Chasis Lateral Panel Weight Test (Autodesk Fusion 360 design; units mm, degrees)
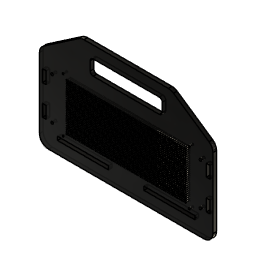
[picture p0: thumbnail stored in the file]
sketch "Sketch1" plane through (0, 0, 0) normal (0, 1, 0) x axis (1, 0, 0)
  line L1 (88.4625, -157.8495) -> (88.4625, -182.8495)
  line L2 (73.4625, -202.8495) -> (-2.8014, -202.7605)
  line L3 (3.9625, -155.3495) -> (292.9625, -155.3495)
  line L4 (3.9625, -91.4325) -> (148.4625, -91.4325)
  line L5 (148.4625, -147.4325) -> (148.4625, -35.4325)
  line L6 (292.9625, -15.4325) -> (3.9625, -15.4325)
  line L7 (262.9625, -141.4325) -> (33.9625, -141.4325)
  line L8 (88.4625, -182.8495) -> (208.4625, -182.8495)
  line L9 (3.9625, -35.4325) -> (292.9625, -35.4325)
  line L10 (292.9625, -91.4325) -> (148.4625, -91.4325)
  line L11 (3.9625, -155.3495) -> (3.9625, -252.9325)
  line L12 (148.4625, -214.9325) -> (148.4625, -182.8495)
  line L13 (223.4625, -202.8495) -> (299.7264, -202.7605)
  line L14 (148.4625, -170.3495) -> (148.4625, -155.3495)
  line L15 (208.4625, -157.8495) -> (88.4625, -157.8495)
  line L16 (3.9625, -147.4325) -> (3.9625, -35.4325)
  line L17 (262.9625, -41.4325) -> (262.9625, -35.4325)
  line L18 (88.4625, -182.8495) -> (208.4625, -157.8495)
  line L19 (3.9625, -147.4325) -> (3.9625, -155.3495)
  line L20 (88.4625, -157.8495) -> (208.4625, -182.8495)
  line L21 (33.9625, -141.4325) -> (33.9625, -147.4325)
  line L22 (33.9625, -41.4325) -> (33.9625, -35.4325)
  line L23 (208.4625, -182.8495) -> (208.4625, -157.8495)
  line L24 (292.9625, -35.4325) -> (292.9625, -15.4325)
  line L25 (292.9625, -155.3495) -> (292.9625, -252.9325)
  line L26 (292.9625, -155.3495) -> (292.9625, -147.4325)
  line L27 (292.9625, -35.4325) -> (292.9625, -147.4325)
  line L28 (262.9625, -141.4325) -> (262.9625, -147.4325)
  line L29 (3.9625, -15.4325) -> (3.9625, -35.4325)
  line L30 (292.9625, -147.4325) -> (3.9625, -147.4325)
  line L31 (262.9625, -147.4325) -> (33.9625, -147.4325)
  line L32 (223.4625, -202.8495) -> (73.4625, -202.8495)
  line L33 (422.8306, -56.4325) -> (416.8306, -56.4325)
  line L34 (470.8306, -141.4325) -> (422.8306, -141.4325)
  line L35 (422.8306, -56.4325) -> (422.8306, -41.4325)
  line L36 (470.8306, -41.4325) -> (422.8306, -41.4325)
  line L37 (550.8306, -41.4325) -> (550.8306, -35.4325)
  line L38 (416.8306, -126.4325) -> (422.8306, -126.4325)
  line L39 (470.8306, -147.4325) -> (470.8306, -141.4325)
  line L40 (684.8306, -147.4325) -> (604.8306, -147.4325)
  line L41 (416.8306, -56.4325) -> (416.8306, -126.4325)
  line L42 (684.8306, -41.4325) -> (732.8306, -41.4325)
  line L43 (422.8306, -126.4325) -> (422.8306, -141.4325)
  line L44 (684.8306, -41.4325) -> (684.8306, -35.4325)
  line L45 (738.8306, -126.4325) -> (732.8306, -126.4325)
  line L46 (604.8306, -147.4325) -> (604.8306, -141.4325)
  line L47 (684.8306, -35.4325) -> (604.8306, -35.4325)
  line L48 (470.8306, -35.4325) -> (470.8306, -41.4325)
  line L49 (732.8306, -126.4325) -> (732.8306, -141.4325)
  line L50 (604.8306, -35.4325) -> (604.8306, -41.4325)
  line L51 (550.8306, -41.4325) -> (604.8306, -41.4325)
  line L52 (550.8306, -141.4325) -> (550.8306, -147.4325)
  line L53 (732.8306, -56.4325) -> (732.8306, -41.4325)
  line L54 (550.8306, -35.4325) -> (470.8306, -35.4325)
  line L55 (732.8306, -56.4325) -> (738.8306, -56.4325)
  line L56 (550.8306, -147.4325) -> (470.8306, -147.4325)
  line L57 (684.8306, -141.4325) -> (684.8306, -147.4325)
  line L58 (738.8306, -56.4325) -> (738.8306, -126.4325)
  line L59 (684.8306, -141.4325) -> (732.8306, -141.4325)
  line L60 (550.8306, -141.4325) -> (604.8306, -141.4325)
  line L61 (3.9625, -155.3495) -> (3.9625, -147.4325)
  line L62 (3.9625, -155.3495) -> (73.4625, -202.8495)
  line L63 (292.9625, -155.3495) -> (223.4625, -202.8495)
  line L64 (292.9625, -155.3495) -> (292.9625, -147.4325)
  line L65 (281.9625, -126.4325) -> (287.9625, -126.4325)
  line L66 (287.9625, -56.4325) -> (281.9625, -56.4325)
  line L67 (8.9625, -126.4325) -> (14.9625, -126.4325)
  line L68 (14.9625, -56.4325) -> (8.9625, -56.4325)
  line L69 (14.9625, -91.4325) -> (281.9625, -91.4325)
  line L70 (148.4625, -71.6893) -> (148.4625, -91.4325)
  line L71 (287.9625, -56.4325) -> (281.9625, -56.4325)
  line L72 (14.9625, -91.4325) -> (281.9625, -91.4325)
  line L73 (281.9625, -126.4325) -> (287.9625, -126.4325)
  line L74 (8.9625, -126.4325) -> (14.9625, -126.4325)
  line L75 (148.4625, -71.6893) -> (148.4625, -91.4325)
  line L76 (14.9625, -56.4325) -> (8.9625, -56.4325)
  line L77 (-57.8702, -329.7432) -> (-63.8702, -329.7432)
  line L78 (-336.8702, -329.7432) -> (-336.8702, -399.7432)
  line L79 (-330.8702, -364.7432) -> (-63.8702, -364.7432)
  line L80 (-63.8702, -399.7432) -> (-57.8702, -399.7432)
  line L81 (-63.8702, -329.7432) -> (-63.8702, -399.7432)
  line L82 (-336.8702, -399.7432) -> (-330.8702, -399.7432)
  line L83 (-57.8702, -399.7432) -> (-57.8702, -329.7432)
  line L84 (-330.8702, -399.7432) -> (-330.8702, -329.7432)
  line L85 (-197.3702, -345) -> (-197.3702, -364.7432)
  line L86 (-330.8702, -329.7432) -> (-336.8702, -329.7432)
  line L87 (732.8306, -106.4325) -> (738.8306, -106.4325)
  line L88 (732.8306, -106.4325) -> (732.8306, -76.4325)
  line L89 (732.8306, -76.4325) -> (738.8306, -76.4325)
  line L90 (422.8306, -106.4325) -> (416.8306, -106.4325)
  line L91 (422.8306, -106.4325) -> (422.8306, -76.4325)
  line L92 (422.8306, -76.4325) -> (416.8306, -76.4325)
  line L93 (732.8306, -91.4325) -> (422.8306, -91.4325)
  line L94 (738.8306, -91.4325) -> (732.8306, -91.4325)
  line L95 (760, -91.4325) -> (738.8306, -91.4325)
  line L96 (-80, -106.4325) -> (416.8306, -106.4325)
  line L97 (-80, -76.4325) -> (416.8306, -76.4325)
  line L98 (8.9625, -106.4325) -> (14.9625, -106.4325)
  line L99 (14.9625, -76.4325) -> (14.9625, -56.4325)
  line L100 (14.9625, -126.4325) -> (14.9625, -106.4325)
  line L101 (8.9625, -106.4325) -> (8.9625, -126.4325)
  line L102 (8.9625, -56.4325) -> (8.9625, -76.4325)
  line L103 (14.9625, -76.4325) -> (14.9625, -56.4325)
  line L104 (14.9625, -126.4325) -> (14.9625, -106.4325)
  line L105 (8.9625, -106.4325) -> (8.9625, -126.4325)
  line L106 (8.9625, -56.4325) -> (8.9625, -76.4325)
  line L107 (281.9625, -106.4325) -> (281.9625, -126.4325)
  line L108 (281.9625, -56.4325) -> (281.9625, -76.4325)
  line L109 (287.9625, -76.4325) -> (287.9625, -56.4325)
  line L110 (287.9625, -126.4325) -> (287.9625, -106.4325)
  line L111 (287.9625, -76.4325) -> (287.9625, -56.4325)
  line L112 (287.9625, -126.4325) -> (287.9625, -106.4325)
  line L113 (281.9625, -106.4325) -> (281.9625, -126.4325)
  line L114 (281.9625, -56.4325) -> (281.9625, -76.4325)
  line L115 (287.9625, -106.4325) -> (281.9625, -106.4325)
  line L116 (284.9625, -91.4325) -> (284.9625, -106.4325)
  line L117 (11.9625, -91.4325) -> (11.9625, -106.4325)
  line L118 (287.9625, -76.4325) -> (281.9625, -76.4325)
  line L119 (14.9625, -76.4325) -> (8.9625, -76.4325)
  line L120 (118.9625, -41.4325) -> (33.9625, -41.4325)
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  point P18 (262.9625, -35.4325)
  point P17 (33.9625, -35.4325)
  point P30 (148.4625, -147.4325)
  point P22 (148.4625, -91.4325)
  point P6 (262.9625, -147.4325)
  point P7 (262.9625, -141.4325)
  point P16 (262.9625, -41.4325)
  point P5 (33.9625, -147.4325)
  point P8 (33.9625, -141.4325)
  point P29 (33.9625, -41.4325)
  point P10 (148.4625, -155.3495)
  point P35 (148.4625, -170.3495)
  point P9 (148.4625, -170.3495)
  point P26 (148.4625, -182.8495)
  point P15 (-2.8014, -202.7605)
  point P36 (299.7264, -202.7605)
  point P13 (73.4625, -202.8495)
  point P37 (223.4625, -202.8495)
  point P20 (3.9625, -91.4325)
  point P81 (148.4625, -91.4325)
  point P93 (148.4625, -91.4325)
  point P103 (-63.8702, -364.7432)
  point P104 (-330.8702, -364.7432)
  point P105 (-197.3702, -364.7432)
  point P115 (422.8306, -91.4325)
  point P116 (732.8306, -91.4325)
  point P118 (738.8306, -91.4325)
  point P122 (14.9625, -106.4325)
  point P123 (8.9625, -106.4325)
  point P92 (14.9625, -91.4325)
  point P124 (281.9625, -106.4325)
  point P91 (281.9625, -91.4325)
  point P125 (287.9625, -106.4325)
  point P79 (281.9625, -91.4325)
  point P126 (284.9625, -106.4325)
  point P128 (11.9625, -106.4325)
  point P130 (287.9625, -76.4325)
  point P131 (281.9625, -76.4325)
  point P132 (14.9625, -76.4325)
  point P133 (8.9625, -76.4325)
  point P129 (11.9625, -91.4325)
  point P134 (11.9625, -91.4325)
  point P127 (284.9625, -91.4325)
  point P135 (284.9625, -91.4325)
  point P140 (148.4625, -38.4325)
  point P142 (148.4625, -38.4325)
  point P3 (292.9625, -15.4325)
  point P19 (292.9625, -35.4325)
  point P2 (3.9625, -147.4325)
  point P24 (3.9625, -35.4325)
  point P14 (292.9625, -155.3495)
  point P27 (292.9625, -147.4325)
  point P32 (208.4625, -182.8495)
  point P33 (88.4625, -182.8495)
  point P28 (88.4625, -157.8495)
  point P4 (3.9625, -15.4325)
  point P63 (470.8306, -141.4325)
  point P64 (470.8306, -147.4325)
  point P42 (416.8306, -126.4325)
  point P57 (422.8306, -126.4325)
  point P47 (550.8306, -35.4325)
  point P61 (470.8306, -35.4325)
  point P40 (470.8306, -41.4325)
  point P48 (422.8306, -41.4325)
  point P53 (550.8306, -41.4325)
  point P58 (604.8306, -41.4325)
  point P66 (416.8306, -56.4325)
  point P51 (422.8306, -141.4325)
  point P1 (0, 0)
  point P71 (287.9625, -126.4325)
  point P72 (281.9625, -126.4325)
  point P74 (287.9625, -56.4325)
  point P75 (14.9625, -126.4325)
  point P76 (8.9625, -126.4325)
  point P78 (14.9625, -56.4325)
  point P83 (287.9625, -126.4325)
  point P84 (281.9625, -126.4325)
  point P85 (287.9625, -56.4325)
  point P89 (14.9625, -126.4325)
  point P90 (8.9625, -126.4325)
  point P88 (14.9625, -56.4325)
  point P95 (-57.8702, -399.7432)
  point P96 (-63.8702, -399.7432)
  point P97 (-57.8702, -329.7432)
  point P101 (-330.8702, -399.7432)
  point P102 (-336.8702, -399.7432)
  point P100 (-330.8702, -329.7432)
  point P108 (732.8306, -106.4325)
  point P109 (738.8306, -106.4325)
  point P110 (732.8306, -76.4325)
  point P114 (738.8306, -76.4325)
  point P136 (118.9625, -41.4325)
  point P137 (177.9625, -41.4325)
  point P138 (118.9625, -35.4325)
  perpendicular L6 L24
  perpendicular L9 L24
  perpendicular L6 L29
  coincident P18 L9
  perpendicular L9 L17
  coincident P17 L9
  perpendicular L9 L22
  perpendicular L9 L16
  perpendicular L24 L30
  perpendicular L9 L27
  midpoint P30 L30
  midpoint P22 L5
  symmetric P6 P18 L10
  symmetric P7 P16 L10
  symmetric P5 P17 L10
  symmetric P8 P29 L10
  perpendicular L26 L30
  perpendicular L3 L26
  perpendicular L19 L30
  midpoint P10 L3
  perpendicular L3 L14
  perpendicular L8 L23
  parallel L1 L23
  parallel L8 L15
  coincident P35 L18
  coincident P35 L20
  coincident P9 P35
  midpoint P26 L8
  perpendicular L8 L12
  perpendicular L3 L25
  perpendicular L3 L11
  symmetric P15 P36 L5
  symmetric P13 P37 L5
  midpoint P20 L16
  parallel L8 L32
  parallel L6 L32
  perpendicular L38 L43
  perpendicular L38 L41
  parallel L36 L54
  parallel L36 L51
  parallel L47 L51
  parallel L42 L47
  equal L37 L48
  equal L44 L50
  equal L45 L55
  equal L47 L54
  equal L35 L43
  parallel L54 L56
  parallel L40 L47
  parallel L42 L59
  parallel L51 L60
  parallel L43 L49
  parallel L35 L53
  equal L36 L42
  equal L48 L50
  equal L41 L58
  equal L35 L53
  equal L43 L49
  collinear L34 L60
  collinear L59 L60
  collinear L47 L54
  collinear L36 L51
  collinear L42 L51
  collinear L40 L56
  collinear L33 L55
  collinear L38 L45
  perpendicular L35 L36
  perpendicular L34 L43
  vertical L35
  horizontal L65
  vertical L113
  horizontal L66
  vertical L109
  horizontal L67
  vertical L101
  horizontal L68
  vertical L99
  perpendicular L69 L99
  midpoint L69 P81
  perpendicular L69 L70
  horizontal L73
  vertical L107
  horizontal L71
  vertical L111
  horizontal L74
  vertical L105
  horizontal L76
  vertical L103
  perpendicular L72 L103
  midpoint P93 L72
  perpendicular L72 L75
  horizontal L80
  vertical L81
  horizontal L77
  vertical L83
  horizontal L82
  vertical L78
  horizontal L86
  vertical L84
  midpoint P103 L81
  midpoint P104 L84
  perpendicular L79 L84
  midpoint P105 L79
  perpendicular L79 L85
  midpoint L91 P115
  midpoint L88 P116
  perpendicular L88 L93
  perpendicular L88 L94
  midpoint L58 P118
  perpendicular L58 L95
  perpendicular L16 L96
  perpendicular L16 L97
  coincident P122 L103
  coincident L96 P122
  coincident L96 P123
  collinear L99 L100
  collinear L101 L102
  collinear L103 L104
  coincident P92 L103
  collinear L105 L106
  coincident L96 P124
  collinear L107 L108
  coincident P91 L107
  coincident L96 P125
  collinear L109 L110
  collinear L111 L112
  collinear L113 L114
  coincident P79 L113
  midpoint L115 P126
  midpoint L98 P128
  coincident L97 P130
  coincident L97 P131
  coincident L97 P132
  coincident L97 P133
  coincident P129 P134
  coincident P127 P135
  perpendicular L22 L120
  coincident L5 P140
  coincident P140 P142
  dimension "d1" distance P3 P19 = 20
  dimension "d2" distance P16 P18 = 6
  dimension "d3" distance P17 P29 = 6
  dimension "d4" distance P2 P24 = 112
  dimension "d5" distance P14 P27 = 7.917 (= "10 mm - 2.083 mm")
  dimension "d6" distance P9 P10 = 15
  dimension "d7" distance P32 P33 = 120
  dimension "d14" distance P28 P33 = 25
  dimension "d18" distance P3 P4 = 289
  dimension "d20" distance P63 P64 = 6
  dimension "d21" distance P42 P57 = 6
  dimension "d22" distance L41 L58 = 322
  dimension "d23" distance P47 P61 = 80
  dimension "d24" distance P40 P48 = 48
  dimension "d25" distance P53 P58 = 54
  dimension "d26" distance P40 P61 = 6
  dimension "d27" distance L42 L59 = 100
  dimension "d28" distance P42 P66 = 70
  dimension "d29" distance P51 P57 = 15
  dimension "d30" distance L8 L32 = 20
  dimension "d31" distance P13 P37 = 150
  dimension "d46" distance P1 L6 = 15.4325
  dimension "d47" distance P71 P72 = 6
  dimension "d48" distance P71 P74 = 70
  dimension "d49" distance P75 P76 = 6
  dimension "d50" distance P75 P78 = 70
  dimension "d51" distance L99 L113 = 267
  dimension "d52" distance P83 P84 = 6
  dimension "d53" distance P83 P85 = 70
  dimension "d54" distance P89 P90 = 6
  dimension "d55" distance P88 P89 = 70
  dimension "d56" distance L103 L107 = 267
  dimension "d57" distance P95 P96 = 6
  dimension "d58" distance P95 P97 = 70
  dimension "d59" distance P101 P102 = 6
  dimension "d60" distance P100 P101 = 70
  dimension "d61" distance L81 L84 = 267
  dimension "d80" distance P108 P109 = 6
  dimension "d81" distance P110 P114 = 6
  dimension "d85" diameter = 3.05
  dimension "d86" diameter = 3.05
  dimension "d87" distance P29 P136 = 85
  dimension "d88" distance P16 P137 = 85
  dimension "d89" distance P136 P138 = 6
  dimension "d90" diameter = 3.05
  dimension "d91" distance L27 L111 = 5
  dimension "d92" distance L100 L113 = 267
  dimension "d93" distance L103 L108 = 267
extrude "Extrude1" new body sketch "Sketch1" along normal blind 6
fillet "Fillet1" radius 15
fillet "Fillet2" radius 15
fillet "Fillet3" radius 15
fillet "Fillet4" radius 15
fillet "Fillet5" radius 15
fillet "Fillet6" radius 15
fillet "Fillet7" radius 5
sketch "Sketch4" plane through (0, 0, 0) normal (0, -1, 0) x axis (1, 0, 0)
  line L1 (281.9625, 126.4325) -> (281.9625, 106.4325)
  line L2 (287.9625, 126.4325) -> (281.9625, 126.4325)
  line L3 (287.9625, 106.4325) -> (287.9625, 126.4325)
  line L4 (281.9625, 106.4325) -> (287.9625, 106.4325)
  line L5 (88.4625, 177.8495) -> (88.4625, 162.8495)
  line L6 (203.4625, 182.8495) -> (93.4625, 182.8495)
  line L7 (208.4625, 162.8495) -> (208.4625, 177.8495)
  line L8 (93.4625, 157.8495) -> (203.4625, 157.8495)
  line L9 (8.9625, 106.4325) -> (14.9625, 106.4325)
  line L10 (8.9625, 126.4325) -> (8.9625, 106.4325)
  line L11 (14.9625, 126.4325) -> (8.9625, 126.4325)
  line L12 (14.9625, 106.4325) -> (14.9625, 126.4325)
  line L13 (8.9625, 76.4325) -> (8.9625, 56.4325)
  line L14 (14.9625, 76.4325) -> (8.9625, 76.4325)
  line L15 (14.9625, 56.4325) -> (14.9625, 76.4325)
  line L16 (8.9625, 56.4325) -> (14.9625, 56.4325)
  line L17 (118.9625, 41.4325) -> (33.9625, 41.4325)
  line L18 (118.9625, 35.4325) -> (118.9625, 41.4325)
  line L19 (33.9625, 35.4325) -> (118.9625, 35.4325)
  line L20 (33.9625, 41.4325) -> (33.9625, 35.4325)
  line L21 (262.9625, 41.4325) -> (177.9625, 41.4325)
  line L22 (262.9625, 35.4325) -> (262.9625, 41.4325)
  line L23 (177.9625, 35.4325) -> (262.9625, 35.4325)
  line L24 (177.9625, 41.4325) -> (177.9625, 35.4325)
  line L25 (281.9625, 76.4325) -> (281.9625, 56.4325)
  line L26 (287.9625, 76.4325) -> (281.9625, 76.4325)
  line L27 (287.9625, 56.4325) -> (287.9625, 76.4325)
  line L28 (281.9625, 56.4325) -> (287.9625, 56.4325)
  line L29 (78.0987, 202.8495) -> (218.8263, 202.8495)
  line L30 (10.4986, 159.8166) -> (69.6349, 200.2335)
  line L31 (3.9625, 30.4325) -> (3.9625, 147.4326)
  line L32 (277.9625, 15.4325) -> (18.9625, 15.4325)
  line L33 (292.9625, 147.4326) -> (292.9625, 30.4325)
  line L34 (227.2902, 200.2335) -> (286.4264, 159.8166)
  line L35 (281.9625, 41.4325) -> (262.9625, 41.4325)
  line L36 (281.9625, 56.4325) -> (281.9625, 41.4325)
  line L37 (271.9625, 41.4325) -> (281.9625, 41.4325)
  line L38 (271.9625, 56.4325) -> (271.9625, 41.4325)
  line L39 (281.9625, 56.4325) -> (271.9625, 56.4325)
  line L40 (281.9625, 41.4325) -> (281.9625, 56.4325)
  line L41 (148.4625, 147.4325) -> (148.4625, 35.4325)
  line L42 (14.9625, 91.4325) -> (281.9625, 91.4325)
  arc A1 centre (93.4625, 162.8495) radius 5 clockwise from (93.4625, 157.8495) to (88.4625, 162.8495)
  arc A2 centre (93.4625, 177.8495) radius 5 clockwise from (88.4625, 177.8495) to (93.4625, 182.8495)
  arc A3 centre (203.4625, 177.8495) radius 5 clockwise from (203.4625, 182.8495) to (208.4625, 177.8495)
  arc A4 centre (203.4625, 162.8495) radius 5 clockwise from (208.4625, 162.8495) to (203.4625, 157.8495)
  arc A5 centre (218.8263, 187.8495) radius 15 clockwise from (218.8263, 202.8495) to (227.2902, 200.2335)
  arc A6 centre (78.0987, 187.8495) radius 15 clockwise from (69.6349, 200.2335) to (78.0987, 202.8495)
  arc A7 centre (18.9625, 147.4326) radius 15 clockwise from (3.9625, 147.4326) to (10.4986, 159.8166)
  arc A8 centre (18.9625, 30.4325) radius 15 clockwise from (18.9625, 15.4325) to (3.9625, 30.4325)
  arc A9 centre (277.9625, 30.4325) radius 15 clockwise from (292.9625, 30.4325) to (277.9625, 15.4325)
  arc A10 centre (277.9625, 147.4326) radius 15 clockwise from (286.4264, 159.8166) to (292.9625, 147.4326)
  circle C1 centre (271.9625, 56.4325) radius 2.05
  circle C2 centre (24.9625, 56.4325) radius 2.05
  circle C3 centre (271.9625, 126.4325) radius 2.05
  circle C4 centre (24.9625, 126.4325) radius 2.05
  point P31 (262.9625, 41.4325)
  point P56 (262.9625, 41.4325)
  point P34 (281.9625, 56.4325)
  point P58 (281.9625, 56.4325)
  point P60 (271.9625, 56.4325)
  point P62 (271.9625, 56.4325)
  point P57 (281.9625, 41.4325)
  point P59 (271.9625, 41.4325)
  point P61 (281.9625, 56.4325)
  coincident P31 P56
  perpendicular L25 L35
  coincident P34 P58
  perpendicular L28 L36
  horizontal L37
  vertical L38
  horizontal L39
  vertical L40
  coincident P60 P62
  symmetric C1 L41 C2
  symmetric C1 L42 C3
  symmetric C2 L42 C4
  dimension "d98" distance P57 P59 = 10
  dimension "d99" distance P57 P61 = 15
  dimension "d100" diameter C1 = 4.1
extrude "Extrude4" cut sketch "Sketch4" profile of C1 C2 C3 C4 no distance stored
sketch "Sketch5" plane through (0, 0, 0) normal (0, -1, 0) x axis (1, 0, 0)
  line L1 (281.9625, 126.4325) -> (281.9625, 106.4325)
  line L2 (287.9625, 126.4325) -> (281.9625, 126.4325)
  line L3 (287.9625, 106.4325) -> (287.9625, 126.4325)
  line L4 (281.9625, 106.4325) -> (287.9625, 106.4325)
  line L5 (88.4625, 177.8495) -> (88.4625, 162.8495)
  line L6 (203.4625, 182.8495) -> (93.4625, 182.8495)
  line L7 (208.4625, 162.8495) -> (208.4625, 177.8495)
  line L8 (93.4625, 157.8495) -> (203.4625, 157.8495)
  line L9 (8.9625, 106.4325) -> (14.9625, 106.4325)
  line L10 (8.9625, 126.4325) -> (8.9625, 106.4325)
  line L11 (14.9625, 126.4325) -> (8.9625, 126.4325)
  line L12 (14.9625, 106.4325) -> (14.9625, 126.4325)
  line L13 (8.9625, 76.4325) -> (8.9625, 56.4325)
  line L14 (14.9625, 76.4325) -> (8.9625, 76.4325)
  line L15 (14.9625, 56.4325) -> (14.9625, 76.4325)
  line L16 (8.9625, 56.4325) -> (14.9625, 56.4325)
  line L17 (118.9625, 41.4325) -> (33.9625, 41.4325)
  line L18 (118.9625, 35.4325) -> (118.9625, 41.4325)
  line L19 (33.9625, 35.4325) -> (118.9625, 35.4325)
  line L20 (33.9625, 41.4325) -> (33.9625, 35.4325)
  line L21 (262.9625, 41.4325) -> (177.9625, 41.4325)
  line L22 (262.9625, 35.4325) -> (262.9625, 41.4325)
  line L23 (177.9625, 35.4325) -> (262.9625, 35.4325)
  line L24 (177.9625, 41.4325) -> (177.9625, 35.4325)
  line L25 (281.9625, 76.4325) -> (281.9625, 56.4325)
  line L26 (287.9625, 76.4325) -> (281.9625, 76.4325)
  line L27 (287.9625, 56.4325) -> (287.9625, 76.4325)
  line L28 (281.9625, 56.4325) -> (287.9625, 56.4325)
  line L29 (78.0987, 202.8495) -> (218.8263, 202.8495)
  line L30 (10.4986, 159.8166) -> (69.6349, 200.2335)
  line L31 (3.9625, 30.4325) -> (3.9625, 147.4326)
  line L32 (277.9625, 15.4325) -> (18.9625, 15.4325)
  line L33 (292.9625, 147.4326) -> (292.9625, 30.4325)
  line L34 (227.2902, 200.2335) -> (286.4264, 159.8166)
  line L35 (3.9625, 41.4325) -> (292.9625, 41.4325)
  line L36 (3.9625, 141.4325) -> (3.9625, 41.4325)
  line L37 (292.9625, 141.4325) -> (3.9625, 141.4325)
  line L38 (292.9625, 41.4325) -> (292.9625, 141.4325)
  line L39 (292.9625, 141.4325) -> (3.9625, 41.4325)
  line L40 (48.4625, 131.4325) -> (49.4625, 131.4325)
  line L41 (248.4625, 51.4325) -> (247.4625, 51.4325)
  line L42 (48.4625, 51.4325) -> (248.4625, 51.4325)
  line L43 (48.4625, 131.4325) -> (48.4625, 51.4325)
  line L44 (248.4625, 131.4325) -> (48.4625, 131.4325)
  line L45 (248.4625, 51.4325) -> (248.4625, 131.4325)
  line L46 (248.4625, 131.4325) -> (48.4625, 51.4325)
  line L47 (48.4625, 131.4325) -> (248.4625, 51.4325)
  line L48 (48.4625, 131.4325) -> (248.4625, 131.4325)
  line L49 (48.4625, 51.4325) -> (48.4625, 131.4325)
  line L50 (248.4625, 51.4325) -> (48.4625, 51.4325)
  line L51 (248.4625, 131.4325) -> (248.4625, 51.4325)
  line L52 (48.4625, 51.4325) -> (248.4625, 131.4325)
  line L53 (248.4625, 51.4325) -> (48.4625, 131.4325)
  line L54 (258.4625, 141.4325) -> (38.4625, 141.4325)
  line L55 (258.4625, 41.4325) -> (258.4625, 141.4325)
  line L56 (38.4625, 41.4325) -> (258.4625, 41.4325)
  line L57 (38.4625, 141.4325) -> (38.4625, 41.4325)
  line L58 (258.4625, 41.4325) -> (38.4625, 141.4325)
  line L59 (38.4625, 41.4325) -> (258.4625, 141.4325)
  line L60 (43.4625, 141.4325) -> (38.4625, 141.4325)
  line L61 (43.4625, 136.4325) -> (43.4625, 141.4325)
  line L62 (38.4625, 136.4325) -> (43.4625, 136.4325)
  line L63 (38.4625, 141.4325) -> (38.4625, 136.4325)
  line L64 (148.4625, 135) -> (148.4625, 141.4325)
  line L65 (43.2994, 91.4325) -> (38.4625, 91.4325)
  circle C1 centre (271.9625, 126.4325) radius 2.05
  circle C2 centre (24.9625, 126.4325) radius 2.05
  circle C3 centre (271.9625, 56.4325) radius 2.05
  circle C4 centre (24.9625, 56.4325) radius 2.05
  arc A1 centre (93.4625, 162.8495) radius 5 clockwise from (93.4625, 157.8495) to (88.4625, 162.8495)
  arc A2 centre (93.4625, 177.8495) radius 5 clockwise from (88.4625, 177.8495) to (93.4625, 182.8495)
  arc A3 centre (203.4625, 177.8495) radius 5 clockwise from (203.4625, 182.8495) to (208.4625, 177.8495)
  arc A4 centre (203.4625, 162.8495) radius 5 clockwise from (208.4625, 162.8495) to (203.4625, 157.8495)
  arc A5 centre (218.8263, 187.8495) radius 15 clockwise from (218.8263, 202.8495) to (227.2902, 200.2335)
  arc A6 centre (78.0987, 187.8495) radius 15 clockwise from (69.6349, 200.2335) to (78.0987, 202.8495)
  arc A7 centre (18.9625, 147.4326) radius 15 clockwise from (3.9625, 147.4326) to (10.4986, 159.8166)
  arc A8 centre (18.9625, 30.4325) radius 15 clockwise from (18.9625, 15.4325) to (3.9625, 30.4325)
  arc A9 centre (277.9625, 30.4325) radius 15 clockwise from (292.9625, 30.4325) to (277.9625, 15.4325)
  arc A10 centre (277.9625, 147.4326) radius 15 clockwise from (286.4264, 159.8166) to (292.9625, 147.4326)
  circle C5 centre (49.4625, 130.4325) radius 1
  circle C6 centre (52.4625, 130.4325) radius 1
  circle C7 centre (55.4625, 130.4325) radius 1
  circle C8 centre (58.4625, 130.4325) radius 1
  circle C9 centre (61.4625, 130.4325) radius 1
  circle C10 centre (64.4625, 130.4325) radius 1
  circle C11 centre (67.4625, 130.4325) radius 1
  circle C12 centre (70.4625, 130.4325) radius 1
  circle C13 centre (73.4625, 130.4325) radius 1
  circle C14 centre (76.4625, 130.4325) radius 1
  circle C15 centre (79.4625, 130.4325) radius 1
  circle C16 centre (82.4625, 130.4325) radius 1
  circle C17 centre (85.4625, 130.4325) radius 1
  circle C18 centre (88.4625, 130.4325) radius 1
  circle C19 centre (91.4625, 130.4325) radius 1
  circle C20 centre (94.4625, 130.4325) radius 1
  circle C21 centre (97.4625, 130.4325) radius 1
  circle C22 centre (100.4625, 130.4325) radius 1
  circle C23 centre (103.4625, 130.4325) radius 1
  circle C24 centre (106.4625, 130.4325) radius 1
  circle C25 centre (109.4625, 130.4325) radius 1
  circle C26 centre (112.4625, 130.4325) radius 1
  circle C27 centre (115.4625, 130.4325) radius 1
  circle C28 centre (118.4625, 130.4325) radius 1
  circle C29 centre (121.4625, 130.4325) radius 1
  circle C30 centre (124.4625, 130.4325) radius 1
  circle C31 centre (127.4625, 130.4325) radius 1
  circle C32 centre (130.4625, 130.4325) radius 1
  circle C33 centre (133.4625, 130.4325) radius 1
  circle C34 centre (136.4625, 130.4325) radius 1
  circle C35 centre (139.4625, 130.4325) radius 1
  circle C36 centre (142.4625, 130.4325) radius 1
  circle C37 centre (145.4625, 130.4325) radius 1
  circle C38 centre (148.4625, 130.4325) radius 1
  circle C39 centre (151.4625, 130.4325) radius 1
  circle C40 centre (154.4625, 130.4325) radius 1
  circle C41 centre (157.4625, 130.4325) radius 1
  circle C42 centre (160.4625, 130.4325) radius 1
  circle C43 centre (163.4625, 130.4325) radius 1
  circle C44 centre (166.4625, 130.4325) radius 1
  circle C45 centre (169.4625, 130.4325) radius 1
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  point P60 (292.9625, 41.4325)
  point P64 (148.4625, 91.4325)
  point P1874 (49.4625, 131.4325)
  point P1884 (148.4625, 91.4325)
  point P969 (148.4625, 91.4325)
  point P1889 (148.4625, 91.4325)
  point P1891 (43.4625, 136.4325)
  point P1893 (43.4625, 136.4325)
  point P1894 (148.4625, 141.4325)
  point P1896 (38.4625, 91.4325)
  point P63 (292.9625, 141.4325)
  point P61 (3.9625, 41.4325)
  point P1875 (48.4625, 131.4325)
  point P1876 (247.4625, 51.4325)
  point P1877 (248.4625, 51.4325)
  point P1882 (48.4625, 51.4325)
  point P1883 (248.4625, 51.4325)
  point P1881 (48.4625, 131.4325)
  point P1887 (258.4625, 41.4325)
  point P1888 (38.4625, 41.4325)
  point P1886 (258.4625, 141.4325)
  point P1885 (38.4625, 141.4325)
  point P1890 (43.4625, 141.4325)
  point P1892 (38.4625, 136.4325)
  horizontal L35
  vertical L36
  horizontal L37
  vertical L38
  coincident L33 P60
  midpoint L39 P64
  coincident C5 P1874
  horizontal L40
  horizontal L41
  horizontal L42
  vertical L43
  horizontal L44
  vertical L45
  horizontal L48
  perpendicular L48 L49
  parallel L48 L50
  parallel L49 L51
  coincident L52 P1884
  coincident L53 P1884
  coincident P969 P1884
  horizontal L54
  perpendicular L54 L55
  parallel L54 L56
  parallel L55 L57
  coincident L58 P1889
  coincident L59 P1889
  coincident P969 P1889
  horizontal L60
  vertical L61
  horizontal L62
  vertical L63
  coincident P1891 P1893
  midpoint L54 P1894
  perpendicular L54 L64
  midpoint L57 P1896
  perpendicular L57 L65
  dimension "d102" distance P60 P63 = 100 (= "85.000 mm + 15 mm")
  dimension "d103" distance P60 P61 = 289
  dimension "d274" diameter C5 = 2
  dimension "d279" distance P1874 P1875 = 1
  dimension "d280" distance P1876 P1877 = 1
  dimension "d281" distance P1882 P1883 = 200
  dimension "d282" distance P1881 P1882 = 80
  dimension "d285" distance P1887 P1888 = 220
  dimension "d286" distance P1886 P1887 = 100
  dimension "d287" distance P1885 P1890 = 5
  dimension "d288" distance P1885 P1892 = 5
  dimension "d289" diameter = 3
  dimension "d277" R-Pattern1-uDistance = 3
  dimension "d278" R-Pattern1-vDistance = -3
extrude "Extrude5" cut sketch "Sketch5" against normal blind 90
sketch "Sketch6" plane through (0, 0, 0) normal (0, -1, 0) x axis (1, 0, 0)
  circle C1 centre (43.4625, 136.4325) radius 1.5
  circle C2 centre (43.4625, 46.4325) radius 1.5
  circle C3 centre (253.4625, 136.4325) radius 1.5
  circle C4 centre (253.4625, 46.4325) radius 1.5
  dimension "d290" diameter C1 = 3
extrude "Extrude6" cut sketch "Sketch6" against normal blind 40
